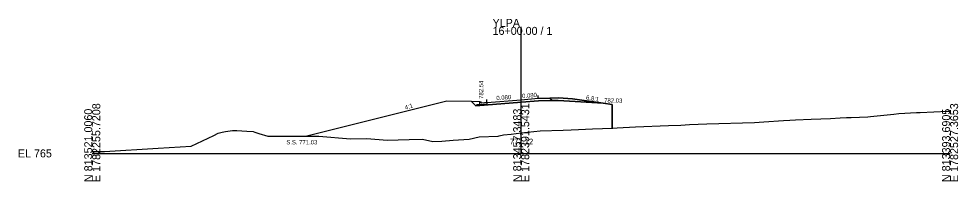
# Model space of a CAD drawing. Extents: x -76 to 1303, y -10 to 9544.
# Drawn here: x -25.7 to 302.8, y 5990.3 to 6047 of the extents above; entities that cross this region are included whole.
import ezdxf

# ---------------------------------------------------------------- set-up
doc = ezdxf.new("R2010")
doc.units = 0
for name, color, linetype in [('Exist Cross Section Cell', 7, 'Continuous'), ('Exist XS Center Line Elevation Label', 7, 'Continuous'), ('Exist XS Ground Line', 7, 'Continuous'), ('Prop XS Ditch Standard Text', 7, 'Continuous'), ('Prop XS Dump Level', 7, 'Continuous'), ('Prop XS Earthwork Shape', 7, 'Continuous'), ('Prop XS EOT Tick Mark', 7, 'Continuous'), ('Prop XS Finish Grade', 7, 'Continuous'), ('Prop XS Finish Grade CurbGutter', 7, 'Continuous'), ('Prop XS Finish Grade Earthwork', 7, 'Continuous'), ('Prop XS Finish Grade Paved Shoulder', 7, 'Continuous'), ('Prop XS Finish Grade Pavement', 7, 'Continuous'), ('Prop XS Hydro Elevations', 7, 'Continuous'), ('Prop XS Pvmt Edge Slope', 7, 'Continuous'), ('Prop XS SE Text', 7, 'Continuous'), ('Prop XS Side Slope Text', 7, 'Continuous'), ('Prop XS SS Elevation Text', 7, 'Continuous'), ('Prop XS Subgrade CurbGutter', 7, 'Continuous'), ('Prop XS Subgrade Earthwork', 7, 'Continuous'), ('Scratch_Level_1', 7, 'Continuous'), ('Scratch_Level_3', 7, 'Continuous')]:
    doc.layers.add(name, color=color, linetype=linetype)

msp = doc.modelspace()

# ---------------------------------------------------------------- linework, layer by layer
at = {"layer": 'Exist Cross Section Cell'}
for p, q in [((150, 6000), (150, 6044.15)), ((0, 6000), (150, 6000)), ((150, 6000), (300, 6000))]:
    msp.add_line(p, q, dxfattribs=at)
at = {"layer": 'Exist XS Ground Line'}
for p, q in [((251.45, 6011.95), (258.12, 6012.22)), ((258.12, 6012.22), (261.59, 6012.43)), ((261.59, 6012.43), (263.81, 6012.48)), ((263.81, 6012.48), (265.43, 6012.54)), ((265.43, 6012.54), (271.29, 6012.78)), ((271.29, 6012.78), (272.18, 6012.85)), ((272.18, 6012.85), (280.27, 6013.74)), ((280.27, 6013.74), (282.02, 6013.88)), ((282.02, 6013.88), (288.28, 6014.25)), ((288.28, 6014.25), (289.09, 6014.3)), ((289.09, 6014.3), (289.56, 6014.32)), ((289.56, 6014.32), (299.14, 6014.68)), ((299.14, 6014.68), (300, 6014.72)), ((182.02, 6008.81), (183.61, 6008.89)), ((183.61, 6008.89), (190.01, 6009.32)), ((190.01, 6009.32), (201.57, 6009.74)), ((201.57, 6009.74), (205.89, 6009.89)), ((205.89, 6009.89), (208.87, 6010.09)), ((208.87, 6010.09), (214.97, 6010.32)), ((214.97, 6010.32), (231.63, 6010.79)), ((231.63, 6010.79), (234.85, 6011.05)), ((234.85, 6011.05), (241.77, 6011.48)), ((241.77, 6011.48), (243.97, 6011.59)), ((243.97, 6011.59), (245.91, 6011.74)), ((245.91, 6011.74), (251.45, 6011.95)), ((34.59, 6002.54), (42.48, 6006.27)), ((42.48, 6006.27), (44.04, 6007.07)), ((44.04, 6007.07), (45.44, 6007.4)), ((45.44, 6007.4), (46.61, 6007.6)), ((46.61, 6007.6), (48.99, 6008.02)), ((48.99, 6008.02), (50.58, 6008)), ((50.58, 6008), (54.09, 6007.78)), ((54.09, 6007.78), (56.3, 6007.69)), ((56.3, 6007.69), (56.89, 6007.41)), ((56.89, 6007.41), (58.2, 6006.99)), ((58.2, 6006.99), (61.35, 6006.03)), ((61.35, 6006.03), (62.64, 6006.03)), ((62.64, 6006.03), (65.69, 6006.03)), ((65.69, 6006.03), (71.9, 6006.03)), ((71.9, 6006.03), (76.3, 6006.03)), ((76.3, 6006.03), (79.21, 6006.03)), ((79.21, 6006.03), (90.29, 6005.12)), ((131.87, 6005.02), (135.35, 6005.74)), ((135.35, 6005.74), (141.97, 6006.03)), ((141.97, 6006.03), (142.34, 6006.08)), ((142.34, 6006.08), (143.87, 6006.51)), ((143.87, 6006.51), (146.47, 6006.71)), ((146.47, 6006.71), (150, 6007.12)), ((150, 6007.12), (156.62, 6007.88)), ((156.62, 6007.88), (164.68, 6008.08)), ((164.68, 6008.08), (167.49, 6008.24)), ((167.49, 6008.24), (170.06, 6008.36)), ((170.06, 6008.36), (174.91, 6008.53)), ((174.91, 6008.53), (182.02, 6008.81)), ((23.09, 6001.84), (34.59, 6002.54)), ((90.29, 6005.12), (96.08, 6005.21)), ((96.08, 6005.21), (103.12, 6004.58)), ((103.12, 6004.58), (110.84, 6004.82)), ((110.84, 6004.82), (115.55, 6004.96)), ((115.55, 6004.96), (119.08, 6004.12)), ((119.08, 6004.12), (122.3, 6004.29)), ((122.3, 6004.29), (126.25, 6004.56)), ((126.25, 6004.56), (131.87, 6005.02)), ((0, 6000.69), (4.25, 6000.7)), ((4.25, 6000.7), (23.09, 6001.84))]:
    msp.add_line(p, q, dxfattribs=at)
at = {"layer": 'Prop XS Dump Level'}
for p, q in [((138, 6017.78), (150, 6018.74)), ((150, 6018.74), (156, 6019.22))]:
    msp.add_line(p, q, dxfattribs=at)
at = {"layer": 'Prop XS Earthwork Shape'}
msp.add_lwpolyline([(143.87, 6006.51), (146.47, 6006.71), (150, 6007.12), (156.62, 6007.88), (164.68, 6008.08), (167.49, 6008.24), (170.06, 6008.36), (174.91, 6008.53), (181.87, 6008.8), (181.87, 6017.03), (178.67, 6017.5), (162.98, 6018.44), (160.9, 6018.4), (156.05, 6018.3), (150.07, 6017.82), (134.16, 6016.55), (132.61, 6018.1), (124, 6018.28), (75.01, 6006.03), (76.3, 6006.03), (79.21, 6006.03), (90.29, 6005.12), (96.08, 6005.21), (103.12, 6004.58), (110.84, 6004.82), (115.55, 6004.96), (119.08, 6004.12), (122.3, 6004.29), (126.25, 6004.56), (131.87, 6005.02), (135.35, 6005.74), (141.97, 6006.03), (142.34, 6006.08)], close=True, dxfattribs=at)
at = {"layer": 'Prop XS EOT Tick Mark'}
for p, q in [((138, 6017.78), (138, 6018.78)), ((156, 6019.22), (156, 6020.22))]:
    msp.add_line(p, q, dxfattribs=at)
at = {"layer": 'Prop XS Finish Grade'}
for p, q in [((160, 6019.3), (163, 6019.36)), ((163, 6019.36), (168, 6019.06)), ((168, 6019.06), (178.67, 6017.5)), ((135.5, 6018.04), (132.61, 6018.1))]:
    msp.add_line(p, q, dxfattribs=at)
at = {"layer": 'Prop XS Finish Grade CurbGutter'}
for p, q in [((135.5, 6018.04), (135.75, 6018.04)), ((135.75, 6018.04), (135.88, 6018.02)), ((135.97, 6017.93), (135.88, 6018.02)), ((136.03, 6017.68), (135.97, 6017.93)), ((136.13, 6017.59), (136.03, 6017.68)), ((136.25, 6017.57), (136.13, 6017.59)), ((138, 6017.78), (136.25, 6017.57))]:
    msp.add_line(p, q, dxfattribs=at)
at = {"layer": 'Prop XS Finish Grade Earthwork'}
for p, q in [((124, 6018.28), (75.01, 6006.03)), ((132.61, 6018.1), (124, 6018.28)), ((178.67, 6017.5), (181.87, 6017.03)), ((181.87, 6017.03), (181.87, 6008.8))]:
    msp.add_line(p, q, dxfattribs=at)
at = {"layer": 'Prop XS Finish Grade Paved Shoulder'}
msp.add_line((156, 6019.22), (160, 6019.3), dxfattribs=at)
at = {"layer": 'Prop XS Finish Grade Pavement'}
for p, q in [((138, 6017.78), (150, 6018.74)), ((150, 6018.74), (156, 6019.22))]:
    msp.add_line(p, q, dxfattribs=at)
at = {"layer": 'Prop XS Pvmt Edge Slope'}
for p, q in [((160, 6019.3), (160.9, 6018.4)), ((134.5, 6016.92), (134.16, 6016.55)), ((135.5, 6017), (134.5, 6016.92))]:
    msp.add_line(p, q, dxfattribs=at)
at = {"layer": 'Prop XS Subgrade CurbGutter'}
for p, q in [((135.5, 6017), (135.5, 6018.04)), ((138, 6017.2), (135.5, 6017)), ((138, 6017.78), (138, 6017.2))]:
    msp.add_line(p, q, dxfattribs=at)
at = {"layer": 'Prop XS Subgrade Earthwork'}
for p, q in [((134.16, 6016.55), (132.61, 6018.1)), ((134.16, 6016.55), (150.07, 6017.82)), ((150.07, 6017.82), (156.05, 6018.3)), ((156.05, 6018.3), (160.9, 6018.4)), ((160.9, 6018.4), (162.98, 6018.44)), ((162.98, 6018.44), (178.67, 6017.5))]:
    msp.add_line(p, q, dxfattribs=at)
at = {"layer": 'Scratch_Level_1'}
msp.add_line((181.87, 6017.03), (181.87, 6008.8), dxfattribs=at)
at = {"layer": 'Scratch_Level_3'}
for p, q in [((163, 6019.36), (160, 6019.3)), ((160, 6019.3), (160.9, 6018.4)), ((168, 6019.06), (163, 6019.36)), ((178.67, 6017.5), (168, 6019.06)), ((160.9, 6018.4), (162.98, 6018.44)), ((162.98, 6018.44), (178.67, 6017.5))]:
    msp.add_line(p, q, dxfattribs=at)

# ---------------------------------------------------------------- texts
at = {"layer": 'Exist Cross Section Cell'}
for s, p in [('YLPA', (140, 6044.15)), ('16+00.00 / 1', (140, 6041.35)), ('EL 765', (-26, 5998.6))]:
    msp.add_text(s, height=2.8, dxfattribs=at).set_placement(p)
for s, p in [('N 813521.0060', (0, 5990)), ('E 1782255.7208', (2.8, 5990)), ('N 813457.3483', (150, 5990)), ('E 1782391.5431', (152.8, 5990)), ('N 813393.6905', (300, 5990)), ('E 1782527.3653', (302.8, 5990))]:
    msp.add_text(s, height=2.8, rotation=90, dxfattribs=at).set_placement(p)
at = {"layer": 'Exist XS Center Line Elevation Label'}
msp.add_text('772.12', height=2, dxfattribs=at).set_placement((146.03, 6003.12))
at = {"layer": 'Prop XS Ditch Standard Text'}
msp.add_text('782.03', height=1.5, dxfattribs=at).set_placement((179.04, 6017.7))
at = {"layer": 'Prop XS Dump Level'}
msp.add_text('Case4', height=0.04, dxfattribs=at).set_placement((168, 6019.02))
at = {"layer": 'Prop XS Hydro Elevations'}
msp.add_text('782.54', height=1.5, rotation=90, dxfattribs=at).set_placement((136.75, 6019.04))
at = {"layer": 'Prop XS SE Text'}
for p in [(141.38, 6018.55), (150.38, 6019.27)]:
    msp.add_text('0.080', height=1.5, rotation=4.5739, dxfattribs=at).set_placement(p)
at = {"layer": 'Prop XS Side Slope Text'}
for s, rotation, p in [('6.8:1', 351.3428, (172.61, 6018.81)), ('4:1', 17.8228, (109.54, 6015.2))]:
    msp.add_text(s, height=1.5, rotation=rotation, dxfattribs=at).set_placement(p)
at = {"layer": 'Prop XS SS Elevation Text'}
msp.add_text('S.S. 771.03', height=1.5, dxfattribs=at).set_placement((67.88, 6003.15))

doc.saveas('drawing.dxf')
